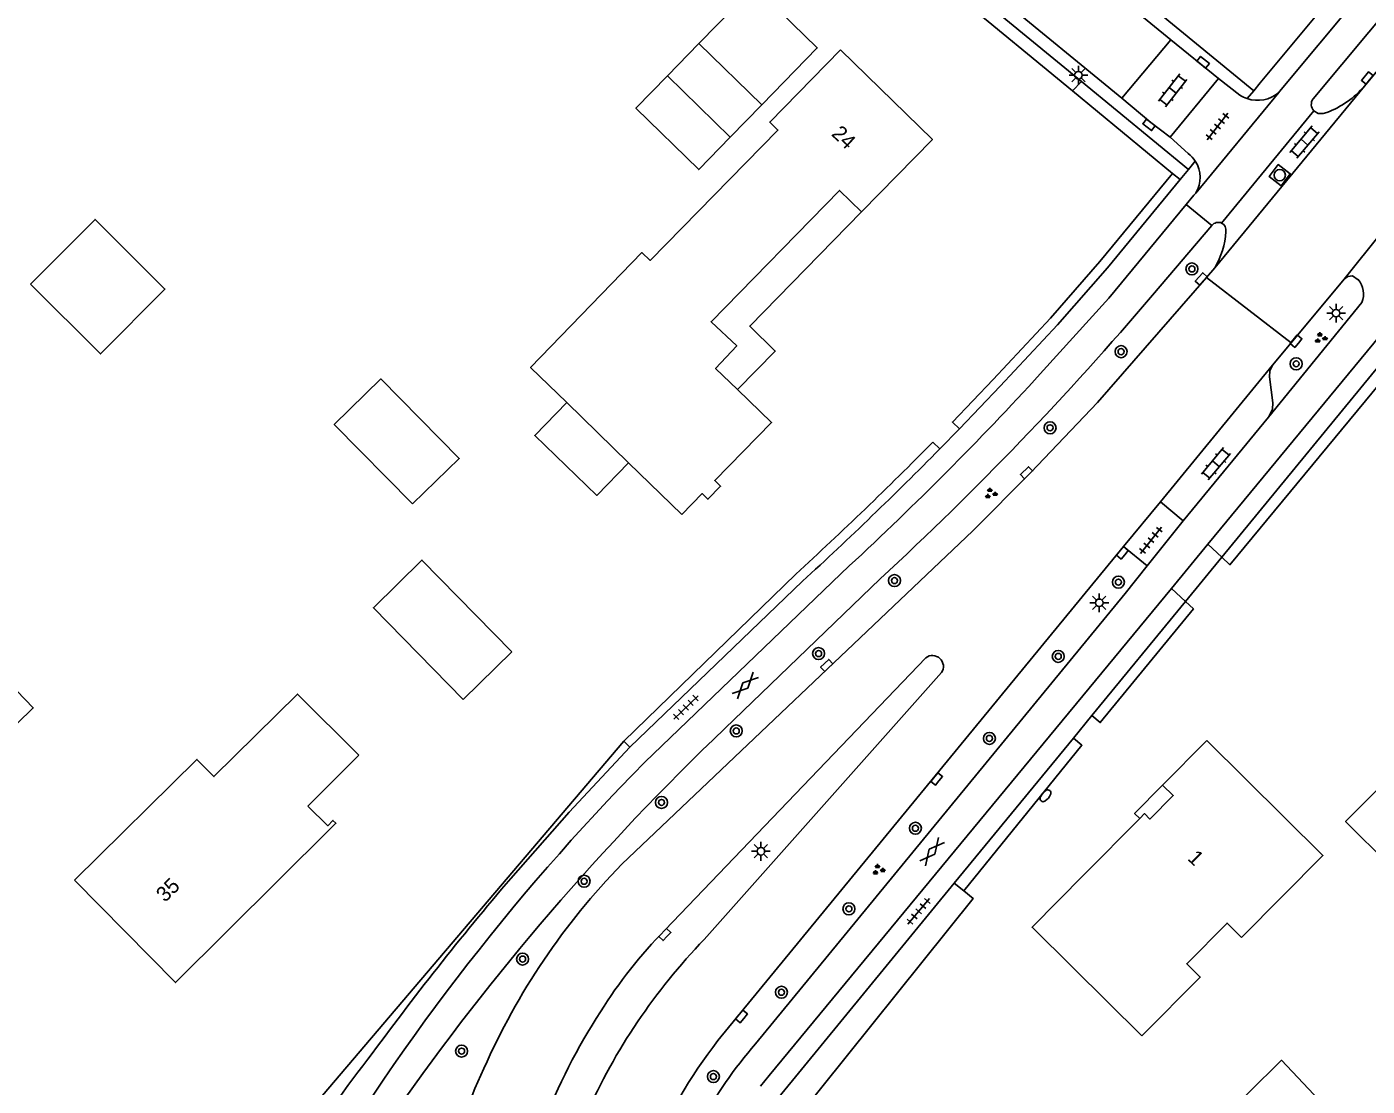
# Model space of a CAD drawing. Extents: x 137999 to 141000, y 397500 to 400501.
# Drawn here: x 138097 to 138186.2, y 398763.7 to 398834.1 of the extents above; entities that cross this region are included whole.
import ezdxf

# ---------------------------------------------------------------- set-up
doc = ezdxf.new("R2010")
doc.units = 0
for name, color, linetype in [('gg-afsc-erfafscheiding', 7, 'Continuous'), ('gg-afsc-hekwerk', 7, 'Continuous'), ('gg-anno-huisnummerreeks BGT', 7, 'Continuous'), ('gg-bbg-bijgebouw', 7, 'Continuous'), ('gg-bbg-gedigitaliseerde bebouwing', 7, 'Continuous'), ('gg-bbg-gedigitaliseerde bijgebouw', 7, 'Continuous'), ('gg-bbg-hoofdgebouw', 7, 'Continuous'), ('gg-bbg-luifel en loopbrug', 7, 'Continuous'), ('gg-knt-verharding', 7, 'Continuous'), ('gg-knt-verharding nz', 7, 'Continuous'), ('gt-grn-groengrens', 7, 'Continuous'), ('gt-grn-weggrens', 7, 'Continuous'), ('gt-symb-boom', 7, 'Continuous'), ('gt-symb-brandkraan', 7, 'Continuous'), ('gt-symb-gesloten verharding', 7, 'Continuous'), ('gt-symb-groenvak', 7, 'Continuous'), ('gt-symb-klinker verharding', 7, 'Continuous'), ('gt-symb-kolk', 7, 'Continuous'), ('gt-symb-lichtmast', 7, 'Continuous'), ('gt-symb-rioolschacht', 7, 'Continuous'), ('gt-symb-tegel verharding', 7, 'Continuous')]:
    doc.layers.add(name, color=color, linetype=linetype)

# ---------------------------------------------------------------- blocks, each defined once
blk = doc.blocks.new('gt0-KOLK')
at = {"layer": 'gt-symb-kolk'}
blk.add_lwpolyline([(0, 0), (0.375, 0), (0.375, 0.4), (-0.375, 0.4), (-0.375, 0), (0, 0)], dxfattribs=at)
blk = doc.blocks.new('gt0-BOOM')
at = {"layer": 'gt-symb-boom'}
for radius in [0.4, 0.2]:
    blk.add_circle((0, 0), radius, dxfattribs=at)
blk = doc.blocks.new('gt0-RS')
at = {"layer": 'gt-symb-rioolschacht'}
blk.add_lwpolyline([(-0.5, -0.5), (0.5, -0.5), (0.5, 0.5), (-0.5, 0.5)], close=True, dxfattribs=at)
blk.add_circle((0, 0), 0.375, dxfattribs=at)
blk = doc.blocks.new('gt0-KL1')
at = {"layer": 'gt-symb-klinker verharding'}
for p, q in [((-1.15, 0.3), (1.15, 0.3)), ((-1, -0.3), (-1, 0.3)), ((-0.5, 0.3), (-0.5, 0.45)), ((0, -0.3), (0, 0.3)), ((0.5, 0.3), (0.5, 0.45)), ((1, -0.3), (1, 0.3)), ((-1.15, -0.3), (1.15, -0.3)), ((-0.5, -0.45), (-0.5, -0.3)), ((0.5, -0.45), (0.5, -0.3))]:
    blk.add_line(p, q, dxfattribs=at)
blk = doc.blocks.new('gt0-TEG1')
at = {"layer": 'gt-symb-tegel verharding'}
for p, q in [((-1.125, 0), (1.125, 0)), ((-0.9, -0.25), (-0.9, 0.25)), ((-0.45, -0.25), (-0.45, 0.25)), ((0, -0.25), (0, 0.25)), ((0.45, -0.25), (0.45, 0.25)), ((0.9, -0.25), (0.9, 0.25))]:
    blk.add_line(p, q, dxfattribs=at)
blk = doc.blocks.new('gt0-GRVAK')
at = {"layer": 'gt-symb-groenvak'}
for p, q in [((-0.11, 0.189), (-0.228, 0.24)), ((-0.182, 0.153), (0.088, 0.153)), ((-0.091, 0.211), (-0.156, 0.322)), ((-0.047, 0.214), (-0.047, 0.393)), ((-0.004, 0.211), (0.061, 0.322)), ((0.015, 0.189), (0.133, 0.24)), ((0.262, -0.052), (0.197, 0.059)), ((0.305, -0.049), (0.305, 0.13)), ((0.349, -0.052), (0.414, 0.059)), ((-0.245, -0.228), (-0.363, -0.177)), ((-0.318, -0.264), (-0.047, -0.264)), ((-0.226, -0.206), (-0.291, -0.095)), ((-0.183, -0.203), (-0.183, -0.024)), ((-0.139, -0.206), (-0.074, -0.095)), ((-0.12, -0.228), (-0.002, -0.177)), ((0.243, -0.074), (0.125, -0.023)), ((0.17, -0.11), (0.441, -0.11)), ((0.368, -0.074), (0.486, -0.023))]:
    blk.add_line(p, q, dxfattribs=at)
blk = doc.blocks.new('gt0-LMAST')
at = {"layer": 'gt-symb-lichtmast'}
for p, q in [((-0.182, 0.173), (-0.447, 0.438)), ((-0.005, 0.246), (-0.005, 0.621)), ((0.172, 0.173), (0.437, 0.438)), ((-0.255, -0.004), (-0.63, -0.004)), ((-0.182, -0.181), (-0.447, -0.446)), ((-0.005, -0.254), (-0.005, -0.629)), ((0.437, -0.446), (0.172, -0.181)), ((0.245, -0.004), (0.62, -0.004))]:
    blk.add_line(p, q, dxfattribs=at)
blk.add_circle((-0.005, -0.004), 0.25, dxfattribs=at)
blk = doc.blocks.new('gt0-GESVH1')
at = {"layer": 'gt-symb-gesloten verharding'}
for p, q in [((-0.992, -0.261), (0.008, 0.239)), ((0.008, -0.261), (-0.992, 0.239)), ((0.008, 0.239), (1.008, -0.261)), ((1.008, 0.239), (0.008, -0.261))]:
    blk.add_line(p, q, dxfattribs=at)
blk = doc.blocks.new('gt0-BR')
at = {"layer": 'gt-symb-brandkraan'}
for centre, radius, start, end in [((-0.244, 0), 0.206, 107.56694, 252.43307), ((0.599, -2.664), 3, 106.89205, 107.56694), ((0, -0.691), 0.938, 73.10799, 106.89205), ((-0.599, -2.664), 3, 72.43309, 73.10799), ((0.244, 0), 0.206, 287.56695, 72.43309), ((0.599, 2.664), 3, 252.43307, 253.10797), ((0, 0.691), 0.938, 253.10797, 286.89206), ((-0.599, 2.664), 3, 286.89206, 287.56695)]:
    blk.add_arc(centre, radius, start, end, dxfattribs=at)

msp = doc.modelspace()

# ---------------------------------------------------------------- linework, layer by layer
at = {"layer": 'gg-afsc-erfafscheiding'}
for p, q in [((138153.499, 398840.58), (138166.563, 398829.802)), ((138173.221, 398824.326), (138166.563, 398829.802)), ((138173.723, 398823.913), (138173.221, 398824.326)), ((138136.747, 398786.596), (138137.14, 398786.187))]:
    msp.add_line(p, q, dxfattribs=at)
at = {"layer": 'gg-afsc-hekwerk'}
msp.add_lwpolyline([(138101.399, 398752.192), (138103.816, 398754.636), (138109.749, 398754.871), (138136.747, 398786.596)], dxfattribs=at)
at = {"layer": 'gg-bbg-bijgebouw'}
msp.add_line((138129.291, 398792.53), (138126.061, 398789.36), dxfattribs=at)
at = {"layer": 'gg-bbg-gedigitaliseerde bebouwing'}
for points in [[(138100.221, 398777.36), (138108.353, 398785.378), (138109.476, 398784.239), (138115.041, 398789.726), (138119.121, 398785.66)], [(138175.501, 398786.65), (138183.224, 398778.993), (138177.816, 398773.551)], [(138171.191, 398767.01), (138175.063, 398770.916), (138174.168, 398771.803), (138176.85, 398774.509), (138177.816, 398773.551)]]:
    msp.add_lwpolyline(points, dxfattribs=at)
at = {"layer": 'gg-bbg-gedigitaliseerde bijgebouw'}
for p, q in [((138141.729, 398832.953), (138139.636, 398830.804)), ((138145.904, 398828.877), (138141.729, 398832.953)), ((138143.811, 398826.728), (138139.636, 398830.804)), ((138143.811, 398826.728), (138145.904, 398828.877))]:
    msp.add_line(p, q, dxfattribs=at)
for points in [[(138097.287, 398816.965), (138101.58, 398821.271), (138106.226, 398816.638), (138101.933, 398812.332), (138097.287, 398816.965)], [(138129.291, 398792.53), (138123.312, 398798.628), (138120.082, 398795.458), (138126.061, 398789.36)], [(138190.52, 398775.502), (138184.724, 398781.26), (138189.572, 398786.14), (138195.368, 398780.383)], [(138176.073, 398761.049), (138180.478, 398765.389), (138185.147, 398760.429), (138180.853, 398756.198), (138176.073, 398761.049)]]:
    msp.add_lwpolyline(points, dxfattribs=at)
at = {"layer": 'gg-bbg-hoofdgebouw'}
for p, q in [((138137.052, 398805.1), (138132.942, 398809.095)), ((138140.601, 398801.65), (138137.052, 398805.1)), ((138172.561, 398783.68), (138175.501, 398786.65)), ((138119.121, 398785.66), (138115.717, 398782.267)), ((138167.341, 398777.73), (138171.044, 398781.461)), ((138171.191, 398767.01), (138166.591, 398771.56))]:
    msp.add_line(p, q, dxfattribs=at)
for points in [[(138151.151, 398832.54), (138146.441, 398827.732), (138146.984, 398827.2), (138138.49, 398818.541), (138137.939, 398819.064), (138130.536, 398811.434), (138132.942, 398809.095)], [(138152.541, 398821.76), (138157.261, 398826.57), (138151.151, 398832.54)], [(138144.294, 398809.958), (138142.841, 398811.36), (138144.251, 398812.87), (138142.541, 398814.47), (138151.081, 398823.19), (138152.541, 398821.76)], [(138140.601, 398801.65), (138141.941, 398803.05), (138142.331, 398802.67), (138143.171, 398803.53), (138142.781, 398803.91), (138146.561, 398807.77), (138144.294, 398809.958)], [(138171.044, 398781.461), (138171.361, 398781.78), (138171.721, 398781.42), (138173.271, 398782.98), (138172.561, 398783.68)], [(138115.717, 398782.267), (138117.049, 398780.97), (138117.398, 398781.328), (138117.589, 398781.142), (138117.221, 398780.78)], [(138117.221, 398780.78), (138106.921, 398770.55), (138100.221, 398777.36)], [(138166.591, 398771.56), (138163.885, 398774.236), (138167.341, 398777.73)]]:
    msp.add_lwpolyline(points, dxfattribs=at)
at = {"layer": 'gg-bbg-luifel en loopbrug'}
for points in [[(138145.904, 398828.877), (138149.594, 398832.665), (138145.419, 398836.742), (138141.729, 398832.953)], [(138139.636, 398830.804), (138137.543, 398828.655), (138141.718, 398824.579), (138143.811, 398826.728)], [(138152.541, 398821.76), (138145.112, 398814.175), (138146.803, 398812.519), (138144.294, 398809.958)], [(138122.684, 398802.359), (138125.789, 398805.389), (138120.591, 398810.664), (138117.486, 398807.634), (138122.684, 398802.359)], [(138132.942, 398809.095), (138130.813, 398806.911), (138134.935, 398802.929), (138137.052, 398805.1)], [(138094.729, 398791.632), (138097.466, 398788.81), (138094.298, 398785.738)], [(138172.561, 398783.68), (138170.704, 398781.796), (138171.044, 398781.461)]]:
    msp.add_lwpolyline(points, dxfattribs=at)
at = {"layer": 'gg-knt-verharding'}
for p, q in [((138084.231, 398899.55), (138169.847, 398829.318)), ((138231.561, 398891.4), (138180.343, 398829.766)), ((138182.571, 398829.28), (138220.448, 398874.857)), ((138221.427, 398872.769), (138185.992, 398830.132)), ((138204.873, 398861.421), (138179.053, 398830.34)), ((138142.162, 398858.591), (138173.101, 398833.196)), ((138178.621, 398829.82), (138163.268, 398842.397)), ((138169.847, 398829.318), (138173.101, 398833.196)), ((138173.101, 398833.196), (138176.27, 398830.635)), ((138167.16, 398830.434), (138166.563, 398829.802)), ((138167.16, 398830.434), (138174.281, 398824.59)), ((138176.27, 398830.635), (138173.056, 398826.731)), ((138185.992, 398830.132), (138176.025, 398818.058)), ((138179.053, 398830.34), (138178.621, 398829.82)), ((138174.767, 398823.022), (138180.284, 398829.695)), ((138180.284, 398829.695), (138180.343, 398829.766)), ((138176.488, 398821.021), (138182.626, 398828.472)), ((138174.281, 398824.59), (138173.723, 398823.913)), ((138174.139, 398822.263), (138174.641, 398822.87)), ((138174.641, 398822.87), (138174.767, 398823.022)), ((138194.3, 398822.368), (138175.576, 398799.694)), ((138175.842, 398820.856), (138171.9, 398816.233)), ((138176.499, 398798.829), (138192.83, 398818.722)), ((138176.025, 398818.058), (138175.491, 398817.41)), ((138184.635, 398817.303), (138181.112, 398813.07)), ((138185.809, 398815.751), (138179.6, 398808.132)), ((138181.112, 398813.07), (138179.867, 398811.573)), ((138179.867, 398811.573), (138172.42, 398802.511)), ((138161.76, 398810.177), (138159.052, 398807.349)), ((138179.6, 398808.132), (138173.927, 398801.238)), ((138159.052, 398807.349), (138157.749, 398806.018)), ((138172.42, 398802.511), (138169.969, 398799.529)), ((138172.42, 398802.511), (138173.927, 398801.238)), ((138171.545, 398798.249), (138173.927, 398801.238)), ((138175.576, 398799.694), (138173.146, 398796.752)), ((138169.969, 398799.529), (138142.991, 398766.7)), ((138171.545, 398798.249), (138169.969, 398799.529)), ((138174.077, 398795.878), (138176.499, 398798.829)), ((138138.143, 398785.2), (138151.73, 398798.242)), ((138170.08, 398796.41), (138171.545, 398798.249)), ((138148.619, 398797.219), (138137.14, 398786.187)), ((138153.775, 398797.373), (138143.45, 398787.44)), ((138170.08, 398796.41), (138145.499, 398766.488)), ((138173.146, 398796.752), (138146.405, 398764.369)), ((138167.855, 398788.299), (138174.077, 398795.878)), ((138156.811, 398792.14), (138139.469, 398774.039)), ((138142.081, 398773.42), (138157.87, 398791.151)), ((138166.627, 398786.802), (138167.855, 398788.299)), ((138158.71, 398777.157), (138166.627, 398786.802)), ((138147.036, 398762.936), (138158.71, 398777.157)), ((138146.405, 398764.369), (138145.831, 398763.67))]:
    msp.add_line(p, q, dxfattribs=at)
for points in [[(138173.056, 398826.731), (138171.779, 398827.711), (138169.847, 398829.318)], [(138182.626, 398828.472), (138182.905, 398828.304), (138183.23, 398828.299), (138183.481, 398828.37)], [(138173.723, 398823.913), (138168.891, 398818.06), (138165.581, 398814.26), (138161.76, 398810.177)], [(138164.431, 398810.996), (138168.991, 398816.03), (138174.139, 398822.263)], [(138184.635, 398817.303), (138184.883, 398817.482), (138185.191, 398817.51), (138185.563, 398817.263)], [(138175.491, 398817.41), (138168.231, 398809.11), (138163.801, 398804.44), (138159.941, 398800.58), (138136.611, 398778.42)], [(138179.6, 398808.132), (138179.87, 398808.647), (138179.9, 398809.084), (138179.665, 398810.796), (138179.689, 398811.204), (138179.867, 398811.573)], [(138137.14, 398786.187), (138133.102, 398781.876), (138129.228, 398777.481)]]:
    msp.add_lwpolyline(points, dxfattribs=at)
for centre, radius, start, end in [((138181.298, 398834.151), 6.179, 290.68572, 319.42992), ((138183.078, 398828.909), 0.628, 143.78058, 224.00757), ((138176.261, 398820.562), 0.512, 63.68642, 144.96965), ((138171.727, 398820.689), 5.039, 328.52804, 357.38728), ((138176.258, 398820.562), 0.513, 348.42351, 63.39422), ((138184.51, 398816.316), 1.417, 336.51376, 41.96817), ((138006.297, 398957.243), 217.505, 312.69116, 319.58581), ((137998.688, 398963.349), 225.127, 312.82822, 317.41037), ((137977.88, 398983.517), 252.702, 312.50472, 315.37996), ((138157.253, 398791.551), 0.736, 327.03967, 126.87551), ((138261.398, 398663.891), 170.81, 133.67131, 144.97275), ((138245.444, 398679.061), 150.927, 135.31184, 149.75881), ((138169.509, 398746.288), 45.986, 135.67418, 156.20294), ((138279.188, 398649.182), 197.354, 139.45113, 143.90183), ((138161.46, 398752.277), 30.938, 135.29916, 148.11709), ((138171.451, 398745.129), 40.78, 136.0715, 155.91278), ((138169.177, 398746.531), 40.534, 146.98222, 170.97108), ((138170.659, 398745.364), 34.939, 142.36329, 157.23873), ((138167.914, 398747.037), 29.678, 139.04988, 164.17548), ((138153.143, 398738.502), 42.935, 141.11097, 164.44255), ((138168.543, 398745.874), 45.277, 155.23104, 165.09085)]:
    msp.add_arc(centre, radius, start, end, dxfattribs=at)
at = {"layer": 'gg-knt-verharding nz'}
for p, q in [((138154.02, 398841.218), (138167.16, 398830.434)), ((138176.27, 398830.635), (138177.696, 398829.528)), ((138174.267, 398825.643), (138173.056, 398826.731)), ((138187.141, 398820.42), (138184.635, 398817.303))]:
    msp.add_line(p, q, dxfattribs=at)
for centre, radius, start, end in [((138178.855, 398831.331), 2.144, 237.26482, 251.7812), ((138178.877, 398831.37), 2.188, 251.55752, 310.02111), ((138173.055, 398824.042), 2.008, 33.12161, 52.8799), ((138173.068, 398824.057), 1.989, 328.66219, 32.96158)]:
    msp.add_arc(centre, radius, start, end, dxfattribs=at)
at = {"layer": 'gt-grn-groengrens'}
for p, q in [((138157.287, 398806.475), (138157.749, 398806.018)), ((138148.169, 398797.688), (138136.747, 398786.596)), ((138158.71, 398777.157), (138159.339, 398776.647))]:
    msp.add_line(p, q, dxfattribs=at)
for points in [[(138173.221, 398824.326), (138168.395, 398818.48), (138165.098, 398814.696), (138161.287, 398810.623), (138158.586, 398807.802), (138159.052, 398807.349)], [(138176.499, 398798.829), (138177.043, 398798.319), (138193.469, 398818.191), (138192.83, 398818.722)], [(138167.855, 398788.299), (138168.419, 398787.836), (138174.61, 398795.379), (138174.077, 398795.878)], [(138159.339, 398776.647), (138167.195, 398786.328), (138166.627, 398786.802)], [(138159.339, 398776.647), (138159.96, 398776.143), (138148.205, 398761.472)]]:
    msp.add_lwpolyline(points, dxfattribs=at)
msp.add_arc((137977.898, 398983.497), 252.027, 312.50138, 315.38047, dxfattribs=at)
at = {"layer": 'gt-grn-weggrens'}
for p, q in [((138178.185, 398829.295), (138178.621, 398829.82)), ((138174.281, 398824.59), (138174.737, 398825.139)), ((138175.842, 398820.856), (138174.139, 398822.263)), ((138175.491, 398817.41), (138181.112, 398813.07)), ((138175.576, 398799.694), (138176.499, 398798.829)), ((138174.077, 398795.878), (138173.146, 398796.752))]:
    msp.add_line(p, q, dxfattribs=at)

# ---------------------------------------------------------------- block references
at = {"layer": 'gt-symb-boom'}
for p in [(138174.511, 398817.977), (138169.799, 398812.479), (138181.444, 398811.671), (138165.078, 398807.42), (138154.734, 398797.263), (138169.623, 398797.164), (138149.691, 398792.417), (138165.626, 398792.23), (138144.216, 398787.277), (138161.044, 398786.78), (138139.244, 398782.524), (138156.123, 398780.807), (138134.097, 398777.288), (138151.704, 398775.453), (138130.006, 398772.116), (138147.218, 398769.909), (138125.952, 398766), (138142.693, 398764.306)]:
    msp.add_blockref('gt0-BOOM', p, dxfattribs=at)
at = {"layer": 'gt-symb-brandkraan', "rotation": -129.35795692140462}
msp.add_blockref('gt0-BR', (138164.774, 398782.969), dxfattribs=at)
at = {"layer": 'gt-symb-gesloten verharding'}
for p, rotation in [((138144.803, 398790.29), 45), ((138157.219, 398779.254), 51.00900595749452)]:
    msp.add_blockref('gt0-GESVH1', p, dxfattribs=dict(at, rotation=rotation))
at = {"layer": 'gt-symb-groenvak'}
for p in [(138183.057, 398813.388), (138161.117, 398803.045), (138153.647, 398778.045)]:
    msp.add_blockref('gt0-GRVAK', p, dxfattribs=at)
at = {"layer": 'gt-symb-klinker verharding'}
for p, rotation in [((138173.228, 398829.846), 51.984339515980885), ((138181.995, 398826.404), 49.98904227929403), ((138176.111, 398805.028), 49.98904227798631)]:
    msp.add_blockref('gt0-KL1', p, dxfattribs=dict(at, rotation=rotation))
at = {"layer": 'gt-symb-kolk'}
for p, rotation in [((138175.128, 398831.554), -39.43862478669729), ((138186.329, 398830.539), 50.275137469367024), ((138171.779, 398827.711), 142.47682811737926), ((138175.285, 398817.176), 48.851804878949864), ((138181.589, 398813.047), 50.597758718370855), ((138163.652, 398804.288), 45), ((138170.041, 398798.985), 50.59775872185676), ((138150.365, 398791.485), 43.54158234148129), ((138157.691, 398783.956), 50.59775871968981), ((138139.607, 398773.61), 45.972395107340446), ((138144.721, 398768.178), 50.59775871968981)]:
    msp.add_blockref('gt0-KOLK', p, dxfattribs=dict(at, rotation=rotation))
at = {"layer": 'gt-symb-lichtmast'}
for p in [(138166.97, 398830.849), (138184.103, 398815.043), (138168.358, 398795.795), (138145.857, 398779.281)]:
    msp.add_blockref('gt0-LMAST', p, dxfattribs=at)
at = {"layer": 'gt-symb-rioolschacht', "rotation": 52.92387968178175}
msp.add_blockref('gt0-RS', (138180.352, 398824.207), dxfattribs=at)
at = {"layer": 'gt-symb-tegel verharding'}
for p, rotation in [((138176.208, 398827.432), 51.98433951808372), ((138171.788, 398799.944), 51.74298312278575), ((138140.861, 398788.837), 44.02760489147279), ((138156.346, 398775.29), 49.98904227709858)]:
    msp.add_blockref('gt0-TEG1', p, dxfattribs=dict(at, rotation=rotation))

# ---------------------------------------------------------------- texts
at = {"layer": 'gg-anno-huisnummerreeks BGT'}
for s, rotation, p in [('24', 315.6, (138150.492, 398826.893)), ('1', 315.2, (138174.168, 398778.759)), ('35', 44.5, (138106.232, 398775.845))]:
    msp.add_text(s, height=1, rotation=rotation, dxfattribs=at).set_placement(p)

doc.saveas('drawing.dxf')
